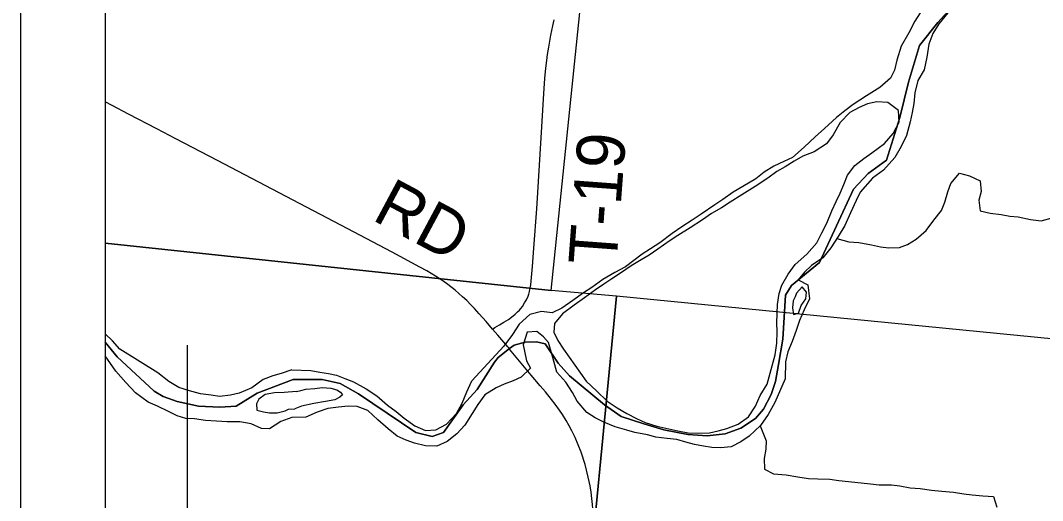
# Model space of a CAD drawing. Extents: x 831 to 1552, y 430 to 870.
# Drawn here: x 1248.77 to 1272.93, y 663.26 to 674.62 of the extents above; entities that cross this region are included whole.
import ezdxf

# ---------------------------------------------------------------- set-up
doc = ezdxf.new("R2010")
doc.units = 0
for name, color, linetype in [('GM_X_Corporation', 7, 'Continuous'), ('GM_X_County_Road', 7, 'Continuous'), ('GM_X_County_Road_Text', 7, 'Continuous'), ('GM_X_Major_River', 7, 'Continuous'), ('GM_X_Minor_River', 7, 'Continuous'), ('GM_X_Township_Road', 7, 'Continuous'), ('GM_X_Township_Road_Text', 7, 'Continuous'), ('SC_Scratch1', 7, 'Continuous'), ('SH_Data', 7, 'Continuous')]:
    doc.layers.add(name, color=color, linetype=linetype)

msp = doc.modelspace()

# ---------------------------------------------------------------- linework, layer by layer
at = {"layer": 'GM_X_Corporation'}
for points in [[(1250.766, 771.115), (1250.766, 667.013), (1251.054, 666.666), (1251.932, 665.853), (1252.144, 665.726), (1252.47, 665.605), (1252.979, 665.499), (1253.482, 665.471), (1253.864, 665.492), (1254.366, 665.804), (1255.217, 666.127), (1255.901, 666.123), (1256.328, 666.031), (1256.756, 665.787), (1258.116, 664.871), (1258.498, 664.779), (1258.773, 664.871), (1259.231, 665.527), (1259.567, 665.894), (1259.973, 666.535), (1260.062, 666.644), (1260.328, 666.859), (1260.444, 666.937), (1260.699, 667.008), (1260.967, 667.018), (1261.176, 666.969), (1261.484, 666.513), (1261.751, 666.215), (1262.576, 665.528), (1262.973, 665.253), (1263.505, 665.081), (1263.982, 664.932), (1264.547, 664.826), (1265.005, 664.795), (1265.433, 664.841), (1265.799, 664.978), (1266.151, 665.207), (1266.334, 665.421), (1266.517, 665.772), (1266.624, 666.078), (1266.691, 666.484), (1266.797, 667.083), (1266.854, 668.12), (1266.998, 668.351), (1267.661, 668.898), (1268.468, 670.627), (1268.814, 671.001), (1269.246, 671.318), (1269.563, 672.326), (1269.764, 673.162), (1270.023, 674.026), (1270.456, 674.573), (1270.773, 674.919)], [(1270.773, 674.919), (1270.456, 674.573), (1270.023, 674.026), (1269.764, 673.162), (1269.563, 672.326), (1269.246, 671.318), (1268.814, 671.001), (1268.468, 670.627), (1267.661, 668.898), (1266.998, 668.351), (1266.854, 668.12), (1266.797, 667.083), (1266.691, 666.484), (1266.624, 666.078), (1266.517, 665.772), (1266.334, 665.421), (1266.151, 665.207), (1265.799, 664.978), (1265.433, 664.841), (1265.005, 664.795), (1264.547, 664.826), (1263.982, 664.932), (1263.505, 665.081), (1262.973, 665.253), (1262.576, 665.528), (1261.751, 666.215), (1261.484, 666.513), (1261.176, 666.969), (1260.967, 667.018), (1260.699, 667.008), (1260.444, 666.937), (1260.328, 666.859), (1260.062, 666.644), (1259.973, 666.535), (1259.567, 665.894), (1259.231, 665.527), (1258.773, 664.871), (1258.498, 664.779), (1258.116, 664.871), (1256.756, 665.787), (1256.328, 666.031), (1255.901, 666.123), (1255.217, 666.127), (1254.366, 665.804), (1253.864, 665.492), (1253.482, 665.471), (1252.979, 665.499), (1252.47, 665.605), (1252.144, 665.726), (1251.932, 665.853), (1251.054, 666.666), (1250.766, 667.013), (1250.766, 650.938)]]:
    msp.add_lwpolyline(points, dxfattribs=at)
for points in [[(1250.766, 689.618), (1250.766, 669.354), (1261.315, 668.229), (1263.383, 688.281)], [(1263.383, 688.281), (1283.584, 686.544), (1281.807, 666.237), (1262.858, 668.098), (1261.315, 668.229)], [(1250.766, 669.354), (1250.766, 650.938), (1261.209, 650.938), (1262.858, 668.098), (1261.315, 668.229)], [(1261.209, 650.938), (1280.498, 650.938), (1281.807, 666.237), (1262.858, 668.098)]]:
    msp.add_lwpolyline(points, close=True, dxfattribs=at)
at = {"layer": 'GM_X_County_Road'}
for points in [[(1259.931, 667.321), (1259.777, 667.501), (1259.617, 667.682), (1259.5, 667.81), (1259.419, 667.896), (1259.319, 667.993), (1259.219, 668.085), (1259.047, 668.238), (1258.871, 668.374), (1258.757, 668.458), (1258.583, 668.571), (1258.379, 668.694), (1258.209, 668.788), (1257.553, 669.141), (1256.345, 669.779), (1253.428, 671.306), (1252.441, 671.823), (1251.993, 672.06), (1251.323, 672.407), (1250.936, 672.611), (1250.766, 672.699)], [(1260.322, 666.861), (1260.311, 666.874), (1260.287, 666.903), (1260.057, 667.173), (1259.931, 667.321)], [(1262.308, 662.971), (1262.307, 662.987), (1262.301, 663.077), (1262.292, 663.173), (1262.276, 663.31), (1262.259, 663.457), (1262.234, 663.613), (1262.194, 663.818), (1262.121, 664.118), (1262.024, 664.411), (1261.882, 664.754), (1261.803, 664.912), (1261.742, 665.03), (1261.672, 665.156), (1261.584, 665.295), (1261.514, 665.398), (1261.408, 665.546), (1261.322, 665.657), (1261.18, 665.832), (1261.057, 665.977), (1260.846, 666.23), (1260.332, 666.848), (1260.322, 666.861)]]:
    msp.add_lwpolyline(points, dxfattribs=at)
at = {"layer": 'GM_X_Major_River'}
for points in [[(1270.038, 674.804), (1269.911, 674.602), (1269.776, 674.331), (1269.594, 674.015), (1269.488, 673.683), (1269.437, 673.448), (1269.341, 673.253), (1269.085, 673.038), (1268.769, 672.839), (1268.46, 672.633), (1268.259, 672.485), (1268.065, 672.322), (1267.778, 672.062), (1267.56, 671.869), (1267.296, 671.624), (1267.025, 671.379), (1266.817, 671.285), (1266.579, 671.176), (1266.355, 671.029), (1266.154, 670.873), (1265.845, 670.69), (1265.622, 670.558), (1265.375, 670.388), (1265.182, 670.263), (1264.865, 670.042), (1264.648, 669.895), (1264.402, 669.74), (1264.177, 669.578), (1263.883, 669.364), (1263.667, 669.216), (1263.467, 669.092), (1263.273, 668.944), (1263.072, 668.796), (1262.818, 668.657), (1262.54, 668.496), (1262.277, 668.304), (1262.084, 668.179), (1261.829, 667.994), (1261.567, 667.817), (1261.336, 667.701), (1261.086, 667.737), (1260.81, 667.667), (1260.562, 667.436), (1260.404, 667.189), (1260.2, 666.919)], [(1270.699, 674.805), (1270.481, 674.543), (1270.338, 674.311), (1270.249, 674.062), (1270.197, 673.751), (1270.137, 673.456), (1269.986, 673.2), (1269.912, 672.913), (1269.89, 672.655), (1269.855, 672.443), (1269.805, 672.223), (1269.714, 671.898), (1269.594, 671.642), (1269.443, 671.379), (1269.17, 671.081), (1268.915, 670.889), (1268.626, 670.561), (1268.531, 670.365), (1268.395, 670.071), (1268.259, 669.77), (1268.101, 669.507), (1267.927, 669.245), (1267.739, 669.006), (1267.469, 668.821), (1267.309, 668.667), (1267.157, 668.486), (1267.386, 668.363), (1267.421, 668.039), (1267.301, 667.776), (1267.189, 667.519), (1267.107, 667.285), (1267.018, 667.029), (1266.913, 666.78), (1266.855, 666.546)], [(1266.615, 666.711), (1266.652, 666.984), (1266.658, 667.257), (1266.655, 667.47), (1266.665, 667.904), (1266.709, 668.161), (1266.766, 668.358), (1266.917, 668.621), (1267.089, 668.845), (1267.361, 669.09), (1267.595, 669.359), (1267.715, 669.599), (1267.834, 669.825), (1267.955, 670.119), (1268.058, 670.337), (1268.146, 670.533), (1268.235, 670.744), (1268.324, 670.963), (1268.496, 671.187), (1268.705, 671.358), (1268.898, 671.49), (1269.2, 671.712), (1269.403, 671.951), (1269.546, 672.214), (1269.529, 672.488), (1269.275, 672.684), (1269.017, 672.697), (1268.795, 672.649), (1268.595, 672.562), (1268.38, 672.445), (1268.146, 672.206), (1267.987, 671.913), (1267.823, 671.704), (1267.537, 671.512), (1267.269, 671.412), (1267.061, 671.295), (1266.845, 671.162), (1266.652, 671.045), (1266.435, 670.89), (1266.142, 670.691), (1265.826, 670.493), (1265.548, 670.324), (1265.34, 670.191), (1265.108, 670.052), (1264.892, 669.905), (1264.606, 669.713), (1264.313, 669.537), (1264.105, 669.397), (1263.834, 669.213), (1263.633, 669.065), (1263.441, 668.955), (1263.209, 668.816), (1262.955, 668.646), (1262.754, 668.506), (1262.561, 668.381), (1262.36, 668.249), (1262.105, 668.057), (1261.857, 667.887), (1261.587, 667.68), (1261.391, 667.448), (1261.379, 667.243), (1261.473, 667.051), (1261.606, 666.843)], [(1267.167, 667.695), (1267.23, 667.877), (1267.338, 668.035), (1267.355, 668.194), (1267.251, 668.317), (1267.12, 668.167), (1267.083, 668.081)], [(1267.083, 668.081), (1267.041, 667.985), (1267.024, 667.826), (1267.045, 667.666), (1267.167, 667.695)], [(1251.118, 666.843), (1250.941, 667.038), (1250.766, 667.206)], [(1260.746, 667.25), (1260.655, 666.95), (1260.685, 666.798), (1260.731, 666.571), (1260.828, 666.394)], [(1261.353, 666.647), (1261.252, 667.003), (1261.133, 667.135), (1260.976, 667.26), (1260.746, 667.25)], [(1255.183, 666.352), (1254.93, 666.267), (1254.731, 666.211), (1254.509, 666.126), (1254.238, 665.927), (1253.939, 665.806), (1253.733, 665.758), (1253.474, 665.727), (1253.277, 665.754), (1253.02, 665.791), (1252.763, 665.858), (1252.515, 665.941), (1252.276, 666.076), (1252.015, 666.287), (1251.118, 666.843)], [(1255.183, 666.352), (1255.633, 666.343), (1255.844, 666.299), (1256.048, 666.271), (1256.243, 666.227), (1256.438, 666.154), (1256.64, 666.072), (1256.938, 665.904), (1257.191, 665.738), (1257.449, 665.518), (1257.649, 665.369), (1257.842, 665.212), (1258.094, 665.03), (1258.348, 664.917), (1258.591, 664.933), (1258.837, 665.07), (1259.079, 665.321), (1259.214, 665.567), (1259.32, 665.837), (1259.441, 666.092), (1260.2, 666.919)], [(1261.606, 666.843), (1262.143, 666.084), (1262.394, 665.849), (1262.637, 665.615), (1262.875, 665.457), (1263.106, 665.321), (1263.337, 665.201), (1263.539, 665.112), (1263.816, 665.021), (1264.313, 664.915), (1264.554, 664.863), (1264.811, 664.856), (1265.061, 664.864), (1265.267, 664.911), (1265.472, 664.966), (1265.74, 665.072), (1265.98, 665.24), (1266.146, 665.493), (1266.259, 665.748), (1266.426, 666.016), (1266.615, 666.711)], [(1255.184, 665.227), (1254.924, 665.135), (1254.654, 664.96), (1254.464, 664.965), (1254.224, 665.077), (1253.952, 665.129), (1253.656, 665.129), (1253.406, 665.143), (1253.14, 665.158), (1252.883, 665.194), (1252.679, 665.207), (1252.475, 665.266), (1252.265, 665.37), (1252.01, 665.498), (1251.785, 665.594), (1251.487, 665.815), (1251.258, 666.056), (1251.021, 666.32), (1250.766, 666.685)], [(1266.855, 666.546), (1266.846, 666.141), (1266.603, 665.586), (1266.443, 665.295), (1266.269, 665.042), (1265.997, 664.785), (1265.797, 664.654), (1265.574, 664.531), (1265.316, 664.508), (1265.112, 664.521), (1264.916, 664.55), (1264.705, 664.586), (1264.502, 664.645), (1264.284, 664.704), (1264.058, 664.733), (1263.794, 664.763), (1263.591, 664.815), (1263.297, 664.876), (1263.102, 664.927), (1262.832, 665.01), (1262.562, 665.117), (1262.353, 665.221), (1262.16, 665.348), (1261.933, 665.612), (1261.818, 665.82), (1261.659, 666.067), (1261.453, 666.3), (1261.353, 666.647)], [(1260.828, 666.394), (1260.61, 666.18), (1260.418, 666.094), (1260.204, 666.017), (1260.012, 665.931), (1259.75, 665.764), (1259.584, 665.534), (1259.45, 665.326), (1259.275, 665.05), (1259.088, 664.843), (1258.855, 664.66), (1258.61, 664.553), (1258.345, 664.561), (1258.082, 664.621), (1257.887, 664.695), (1257.678, 664.784), (1257.463, 664.957), (1257.22, 665.176), (1256.984, 665.395), (1256.729, 665.486), (1256.517, 665.492), (1256.29, 665.475), (1256.031, 665.437), (1255.779, 665.353), (1255.511, 665.232), (1255.184, 665.227)], [(1255.294, 665.845), (1255.393, 665.865), (1255.515, 665.899), (1255.727, 665.916), (1255.902, 665.941), (1256.106, 665.92), (1256.249, 665.886), (1256.338, 665.83), (1256.381, 665.761), (1256.319, 665.71), (1256.204, 665.645), (1255.976, 665.606), (1255.702, 665.56), (1255.412, 665.492), (1255.251, 665.429)], [(1255.294, 665.845), (1255, 665.82), (1254.775, 665.811), (1254.554, 665.768), (1254.4, 665.665), (1254.345, 665.552), (1254.357, 665.4), (1254.512, 665.36), (1254.659, 665.341), (1254.833, 665.337), (1255.024, 665.386), (1255.106, 665.421), (1255.251, 665.429)]]:
    msp.add_lwpolyline(points, dxfattribs=at)
at = {"layer": 'GM_X_Minor_River'}
for points in [[(1268.069, 669.46), (1268.358, 669.382), (1268.593, 669.372), (1268.889, 669.315), (1269.101, 669.267), (1269.298, 669.242), (1269.549, 669.247), (1269.74, 669.32), (1269.946, 669.447), (1270.184, 669.649), (1270.362, 669.898), (1270.547, 670.123), (1270.626, 670.32), (1270.697, 670.57), (1270.768, 670.766), (1270.968, 671.007), (1271.211, 670.943), (1271.46, 670.826), (1271.48, 670.576), (1271.431, 670.371), (1271.459, 670.12), (1271.694, 670.064), (1271.959, 670.031), (1272.164, 669.991), (1272.361, 669.973), (1272.649, 669.909), (1272.899, 669.883), (1273.166, 669.948)], [(1260.139, 666.527), (1260.139, 666.528)], [(1266.258, 665.031), (1266.4, 664.675), (1266.394, 664.481), (1266.353, 664.261), (1266.357, 664.004), (1266.575, 663.895), (1266.87, 663.869), (1267.149, 663.827), (1267.398, 663.786), (1267.625, 663.776), (1267.904, 663.765), (1268.116, 663.74), (1268.35, 663.714), (1268.863, 663.662), (1269.074, 663.637), (1269.362, 663.634), (1269.558, 663.609), (1269.807, 663.56), (1270.041, 663.55), (1270.305, 663.509), (1270.554, 663.483), (1270.826, 663.457), (1271.075, 663.423), (1271.271, 663.398), (1271.52, 663.372), (1271.777, 663.362), (1271.85, 663.103)]]:
    msp.add_lwpolyline(points, dxfattribs=at)
at = {"layer": 'GM_X_Township_Road'}
msp.add_lwpolyline([(1259.931, 667.321), (1259.986, 667.354), (1260.091, 667.419), (1260.194, 667.482), (1260.304, 667.549), (1260.417, 667.632), (1260.465, 667.672), (1260.523, 667.724), (1260.565, 667.765), (1260.598, 667.805), (1260.635, 667.854), (1260.688, 667.937), (1260.734, 668.015), (1260.769, 668.096), (1260.787, 668.143), (1260.804, 668.205), (1260.812, 668.254), (1260.834, 668.369), (1260.875, 668.802), (1260.906, 669.237), (1260.975, 670.168), (1261.08, 671.844), (1261.145, 672.895), (1261.168, 673.247), (1261.19, 673.495), (1261.21, 673.676), (1261.227, 673.818), (1261.257, 673.993), (1261.283, 674.136), (1261.31, 674.272), (1261.355, 674.498), (1261.387, 674.64)], dxfattribs=at)
at = {"layer": 'SC_Scratch1'}
msp.add_line((1252.705, 666.938), (1252.705, 620.925), dxfattribs=at)
at = {"layer": 'SH_Data'}
for p, q in [((1248.766, 788.938), (1248.766, 648.938)), ((1250.766, 786.938), (1250.766, 650.938))]:
    msp.add_line(p, q, dxfattribs=at)

# ---------------------------------------------------------------- texts
at = {"layer": 'GM_X_County_Road_Text'}
msp.add_text('RD', height=1.1364, rotation=331.8986, dxfattribs=at).set_placement((1257.049, 669.919))
at = {"layer": 'GM_X_Township_Road_Text'}
msp.add_text('T-19', height=1.1364, rotation=85.7631, dxfattribs=at).set_placement((1262.855, 668.807))

doc.saveas('drawing.dxf')
